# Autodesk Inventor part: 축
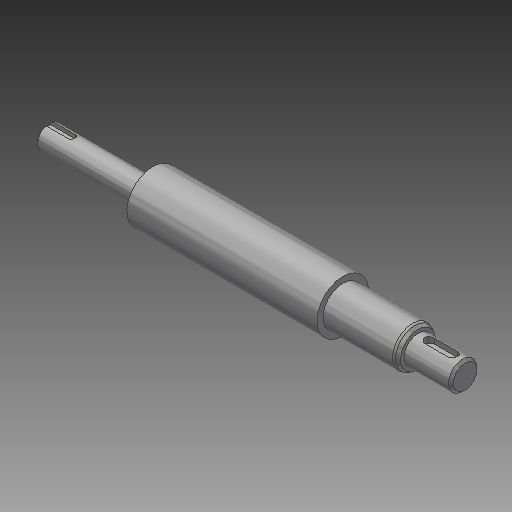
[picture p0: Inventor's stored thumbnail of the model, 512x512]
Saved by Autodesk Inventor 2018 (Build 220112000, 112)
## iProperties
Created: 2016-05
Part Number: 축
Document SubType Name: Modeling
Designer: mduedu
Density: 7.86 g/cm^3
Material: 강철, 연강
Appearance: 강철
Author: mduedu
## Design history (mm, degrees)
sketch "스케치1"
  geometry: L1 (-44, 11)-(-44, 5); L2 (37, 11)-(37, 8.5); L3 (-89, 0)-(89, 0); L4 (-44, 11)-(37, 11); L5 (37, 11)-(37, 8.5); L6 (-44, 11)-(-44, 5); L7 (-44, 5)-(-89, 5); L8 (-89, 5)-(-89, 0); L9 (37, 8.5)-(69, 8.5); L10 (89, 6)-(89, 0); L11 (69, 8.5)-(69, 6); L12 (69, 6)-(89, 6); 1 further point
  constraints: 24 end point, 9 perpendicular, 2 midpoint, 1 horizontal
  dimensions: "d0" = 22 diameter of L4 L3; "d1" = 10 diameter of L7 L3; "d2" = 45 distance between parallel lines of L8 L1; "d3" = 52 distance between parallel lines of L10 L2; "d4" = 12 diameter of L12 L3; "d5" = 20 distance between parallel lines of L10 L11; "d29" = 81 distance of L1.start L2.start; "d37" = 17 diameter of L9 L3
revolve "회전1" stored, may be unused: angle "d6" = 90 deg
chamfer "모따기2" distance "d32" = 1; stored, may be unused: second distance "d33" = 2, angle "d34" = 45 deg
node "작업 평면4"
sketch "스케치4"
  geometry: L1 (-5, 2)-(5, 2); L2 (5, -2)-(-5, -2); L3 (-10, -5)-(-10, 5) reference; A1 r 2 centre (5, 0) between (5, -2) and (5, 2); A2 r 2 centre (-5, 0) between (-5, 2) and (-5, -2); 1 further point
  constraints: 4 end point, 4 point on circle, 4 tangent, 2 centre point, 1 horizontal, 1 horizontal alignment, 1 parallel
  dimensions: "d20" = 4 distance between parallel lines of L2 L1; "d21" = 14 dimension on A1 A2; "d35" = 3 distance edge to line of A2 L3
extrude "돌출3" cut sketch "스케치4" distance "d23" = 2.5; taper "d24" = 0 deg
node "작업 평면5"
sketch "스케치5"
  geometry: L1 (22.5, 1.5)-(12, 1.5); L2 (12, -1.5)-(22.5, -1.5); L3 (22.5, 4)-(22.5, -4) reference; A1 r 1.5 centre (12, 0) between (12, 1.5) and (12, -1.5); 3 further points
  constraints: 4 end point, 2 horizontal alignment, 2 point on circle, 2 point on line, 2 tangent, 1 centre point, 1 coincident, 1 horizontal, 1 midpoint
  dimensions: "d25" = 3 distance between parallel lines of L2 L1; "d36" = 12 dimension on A1 L3
extrude "돌출4" cut sketch "스케치5" distance "d27" = 1.8; taper "d28" = 0 deg
chamfer "모따기3" distance "d38" = 1.82; stored, may be unused: second distance "d39" = 2, angle "d40" = 30 deg
fillet "모깎기1" dims "d41" = 2
node "솔리드1"
